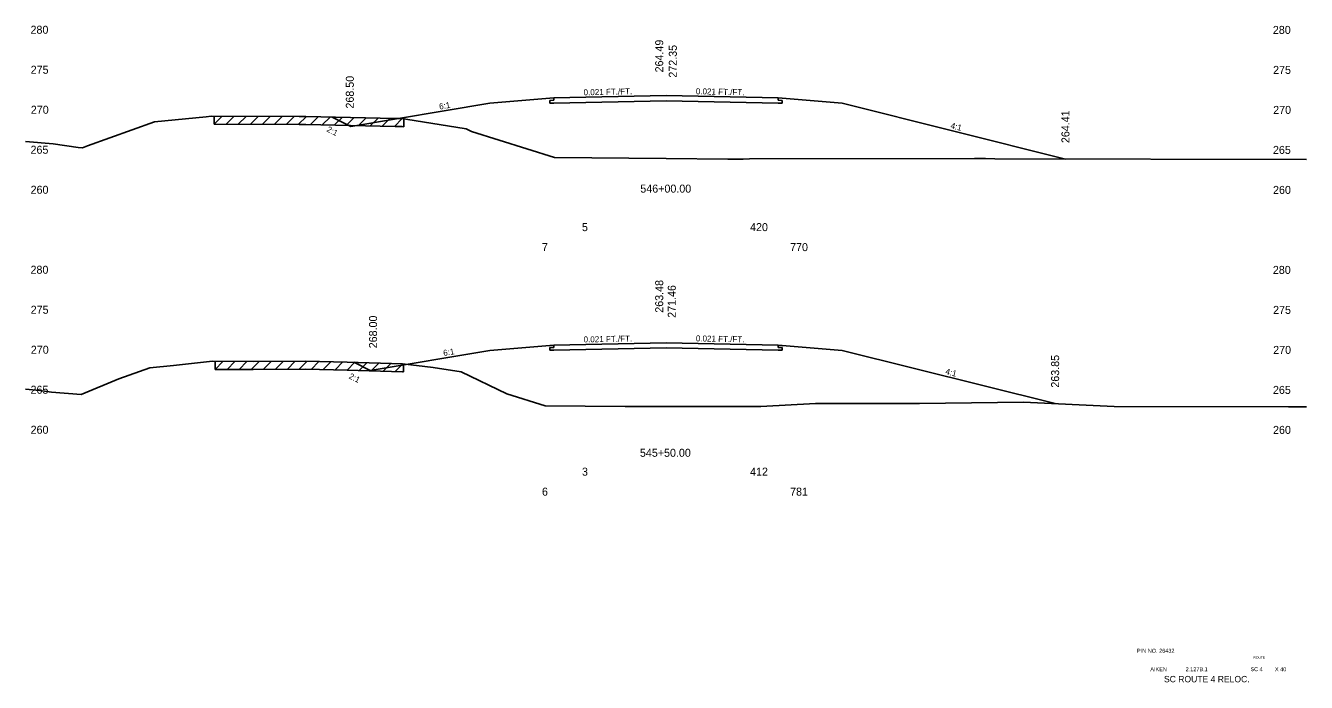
# Model space of a CAD drawing. Extents: x 2967 to 4323, y -3677 to -817.
# Drawn here: x 3555.3 to 3715.3, y -1970.8 to -1888.7 of the extents above; entities that cross this region are included whole.
import ezdxf

# ---------------------------------------------------------------- set-up
doc = ezdxf.new("R2010")
doc.units = 0
for name, color, linetype in [('Level 1', 7, 'Continuous'), ('Level 10', 7, 'Continuous'), ('Level 11', 7, 'Continuous'), ('Level 12', 7, 'Continuous'), ('Level 20', 7, 'Continuous'), ('Level 3', 7, 'Continuous'), ('Level 32', 7, 'Continuous'), ('Level 33', 7, 'Continuous'), ('Level 59', 7, 'Continuous'), ('Level 6', 7, 'Continuous'), ('Level 60', 7, 'Continuous'), ('Level 61', 7, 'Continuous'), ('Level 7', 7, 'Continuous')]:
    doc.layers.add(name, color=color, linetype=linetype)

msp = doc.modelspace()

# ---------------------------------------------------------------- linework, layer by layer
at = {"layer": 'Level 11'}
for p, q in [((3621.35, -1898.08), (3620.85, -1898.1)), ((3620.85, -1898.1), (3620.85, -1898.44)), ((3620.85, -1898.44), (3621.35, -1898.42)), ((3621.35, -1897.78), (3621.35, -1898.08)), ((3649.35, -1898.08), (3649.35, -1897.78)), ((3649.85, -1898.1), (3649.35, -1898.08)), ((3649.35, -1898.42), (3649.85, -1898.44)), ((3649.85, -1898.44), (3649.85, -1898.1)), ((3621.35, -1928.98), (3620.85, -1928.99)), ((3620.85, -1928.99), (3620.85, -1929.33)), ((3620.85, -1929.33), (3621.35, -1929.32)), ((3621.35, -1928.68), (3621.35, -1928.98)), ((3649.35, -1928.98), (3649.35, -1928.68)), ((3649.85, -1928.99), (3649.35, -1928.98)), ((3649.35, -1929.32), (3649.85, -1929.33)), ((3649.85, -1929.33), (3649.85, -1928.99))]:
    msp.add_line(p, q, dxfattribs=at)
at = {"layer": 'Level 12'}
for p, q in [((3635.35, -1898.13), (3621.35, -1898.42)), ((3649.35, -1898.42), (3635.35, -1898.13)), ((3635.35, -1929.03), (3621.35, -1929.32)), ((3649.35, -1929.32), (3635.35, -1929.03))]:
    msp.add_line(p, q, dxfattribs=at)
at = {"layer": 'Level 59'}
for p, q in [((3621.35, -1897.78), (3635.35, -1897.49)), ((3635.35, -1897.49), (3649.35, -1897.78)), ((3621.35, -1928.68), (3635.35, -1928.39)), ((3635.35, -1928.39), (3649.35, -1928.68))]:
    msp.add_line(p, q, dxfattribs=at)
at = {"layer": 'Level 6'}
for p, q in [((3613.35, -1898.45), (3621.35, -1897.78)), ((3649.35, -1897.78), (3657.35, -1898.45)), ((3613.35, -1929.34), (3621.35, -1928.68)), ((3649.35, -1928.68), (3657.35, -1929.34))]:
    msp.add_line(p, q, dxfattribs=at)
at = {"layer": 'Level 60'}
for p, q in [((3563.08, -1903.76), (3571.46, -1900.77)), ((3571.46, -1900.77), (3577.89, -1900.13)), ((3577.89, -1900.13), (3578.52, -1900.07)), ((3578.52, -1900.07), (3589.52, -1900.12)), ((3589.52, -1900.12), (3590.35, -1900.12)), ((3590.35, -1900.12), (3601.53, -1900.34)), ((3601.53, -1900.34), (3602.37, -1900.37)), ((3602.37, -1900.37), (3602.84, -1900.43)), ((3602.84, -1900.43), (3610.37, -1901.64)), ((3610.37, -1901.64), (3611.06, -1901.97)), ((3611.06, -1901.97), (3621.42, -1905.22)), ((3555.35, -1903.22), (3558.79, -1903.54)), ((3558.79, -1903.54), (3561.93, -1903.98)), ((3561.93, -1903.98), (3562.44, -1904.03)), ((3562.44, -1904.03), (3563.08, -1903.76)), ((3621.42, -1905.22), (3635.35, -1905.35)), ((3635.35, -1905.35), (3643.06, -1905.42)), ((3643.06, -1905.42), (3644.99, -1905.42)), ((3644.99, -1905.42), (3645.76, -1905.38)), ((3645.76, -1905.38), (3673.89, -1905.37)), ((3673.89, -1905.37), (3675.25, -1905.35)), ((3675.25, -1905.35), (3676.43, -1905.41)), ((3676.43, -1905.41), (3715.35, -1905.48)), ((3573.84, -1931.23), (3578.71, -1930.7)), ((3578.71, -1930.7), (3583.78, -1930.73)), ((3583.78, -1930.73), (3590.35, -1930.7)), ((3590.35, -1930.7), (3595.51, -1930.8)), ((3595.51, -1930.8), (3602.42, -1931.02)), ((3602.42, -1931.02), (3606.28, -1931.47)), ((3567.01, -1932.9), (3570.87, -1931.52)), ((3570.87, -1931.52), (3573.84, -1931.23)), ((3606.28, -1931.47), (3609.76, -1932.03)), ((3609.76, -1932.03), (3615.46, -1934.76)), ((3555.35, -1934.2), (3557.12, -1934.37)), ((3557.12, -1934.37), (3558.58, -1934.58)), ((3562.27, -1934.87), (3567.01, -1932.9)), ((3558.58, -1934.58), (3562.27, -1934.87)), ((3615.46, -1934.76), (3620.24, -1936.26)), ((3647.21, -1936.37), (3654.03, -1935.97)), ((3654.03, -1935.97), (3667.01, -1935.97)), ((3667.01, -1935.97), (3680.02, -1935.8)), ((3680.02, -1935.8), (3691.33, -1936.37)), ((3620.24, -1936.26), (3630.25, -1936.36)), ((3630.25, -1936.36), (3635.35, -1936.36)), ((3635.35, -1936.36), (3647.21, -1936.37)), ((3691.33, -1936.37), (3713.13, -1936.4)), ((3713.13, -1936.4), (3715.35, -1936.4))]:
    msp.add_line(p, q, dxfattribs=at)
at = {"layer": 'Level 61'}
for p, q in [((3579.91, -1900.07), (3578.91, -1901.07)), ((3578.91, -1900.07), (3578.91, -1901.07)), ((3581.41, -1900.08), (3580.41, -1901.08)), ((3582.91, -1900.09), (3581.91, -1901.08)), ((3584.41, -1900.1), (3583.41, -1901.09)), ((3585.91, -1900.1), (3584.91, -1901.1)), ((3587.41, -1900.11), (3586.41, -1901.1)), ((3588.91, -1900.12), (3587.91, -1901.11)), ((3590.42, -1900.12), (3589.41, -1901.12)), ((3591.89, -1900.15), (3590.91, -1901.13)), ((3593.39, -1900.18), (3592.41, -1901.16)), ((3594.89, -1900.21), (3593.91, -1901.19)), ((3596.39, -1900.24), (3595.41, -1901.22)), ((3597.89, -1900.27), (3596.91, -1901.25)), ((3599.39, -1900.3), (3598.41, -1901.28)), ((3600.89, -1900.33), (3599.91, -1901.31)), ((3602.38, -1900.37), (3601.41, -1901.34)), ((3602.58, -1901.39), (3602.58, -1900.39)), ((3578.91, -1901.07), (3589.52, -1901.12)), ((3589.52, -1901.12), (3590.35, -1901.12)), ((3590.35, -1901.12), (3601.53, -1901.34)), ((3601.53, -1901.34), (3602.37, -1901.37)), ((3602.37, -1901.37), (3602.58, -1901.39)), ((3580, -1930.71), (3579.01, -1931.71)), ((3579.01, -1930.71), (3579.01, -1931.71)), ((3581.5, -1930.72), (3580.51, -1931.71)), ((3583, -1930.73), (3582.01, -1931.72)), ((3584.51, -1930.73), (3583.51, -1931.73)), ((3586.01, -1930.72), (3585.01, -1931.72)), ((3587.51, -1930.71), (3586.51, -1931.72)), ((3589.01, -1930.7), (3588.01, -1931.71)), ((3590.51, -1930.7), (3589.51, -1931.7)), ((3591.99, -1930.73), (3591.01, -1931.71)), ((3593.49, -1930.76), (3592.51, -1931.74)), ((3594.99, -1930.79), (3594.01, -1931.77)), ((3596.48, -1930.83), (3595.51, -1931.8)), ((3597.98, -1930.88), (3597.01, -1931.85)), ((3599.48, -1930.92), (3598.51, -1931.89)), ((3600.98, -1930.97), (3600.01, -1931.94)), ((3602.47, -1931.02), (3601.51, -1931.99)), ((3602.55, -1932.03), (3602.55, -1931.03)), ((3579.01, -1931.71), (3583.78, -1931.73)), ((3583.78, -1931.73), (3590.35, -1931.7)), ((3590.35, -1931.7), (3595.51, -1931.8)), ((3595.51, -1931.8), (3602.42, -1932.02)), ((3602.42, -1932.02), (3602.55, -1932.03))]:
    msp.add_line(p, q, dxfattribs=at)
at = {"layer": 'Level 7'}
for p, q in [((3595.98, -1901.35), (3613.35, -1898.45)), ((3657.35, -1898.45), (3685.25, -1905.43)), ((3595.98, -1901.35), (3593.65, -1900.18)), ((3598.39, -1931.84), (3613.35, -1929.34)), ((3657.35, -1929.34), (3683.96, -1936)), ((3598.39, -1931.84), (3596.37, -1930.83))]:
    msp.add_line(p, q, dxfattribs=at)

# ---------------------------------------------------------------- texts
at = {"layer": 'Level 1'}
for s, p in [('5', (3624.85, -1914.43)), ('420', (3645.85, -1914.43)), ('7', (3619.85, -1916.93)), ('770', (3650.85, -1916.93)), ('3', (3624.85, -1945)), ('412', (3645.85, -1945)), ('6', (3619.85, -1947.5)), ('781', (3650.85, -1947.5))]:
    msp.add_text(s, height=1, dxfattribs=at).set_placement(p)
at = {"layer": 'Level 10'}
for s, p in [('264.49', (3635, -1894.59)), ('263.48', (3635, -1924.63))]:
    msp.add_text(s, height=1, rotation=90, dxfattribs=at).set_placement(p)
for s, p in [('546+00.00', (3632.14, -1909.62)), ('545+50.00', (3632.09, -1942.64))]:
    msp.add_text(s, height=1, dxfattribs=at).set_placement(p)
at = {"layer": 'Level 20'}
for s, height, p in [('PIN NO. 26432', 0.5, (3694.19, -1967.14)), ('ROUTE', 0.3, (3708.73, -1967.88)), ('AIKEN', 0.5, (3695.85, -1969.44)), (' 2.127B.1', 0.5, (3700.07, -1969.44)), ('SC 4', 0.5, (3708.36, -1969.44)), ('X 40', 0.5, (3711.42, -1969.45)), ('SC ROUTE 4 RELOC.', 0.8, (3697.56, -1970.83))]:
    msp.add_text(s, height=height, dxfattribs=at).set_placement(p)
at = {"layer": 'Level 3'}
for s, p in [(' 280', (3555.59, -1889.76)), (' 280', (3710.79, -1889.78)), (' 275', (3555.61, -1894.76)), (' 275', (3710.82, -1894.78)), (' 270', (3555.63, -1899.76)), (' 270', (3710.83, -1899.78)), (' 265', (3555.59, -1904.76)), (' 265', (3710.8, -1904.78)), (' 260', (3555.6, -1909.76)), (' 260', (3710.81, -1909.78)), (' 280', (3555.59, -1919.76)), (' 280', (3710.79, -1919.78)), (' 275', (3555.61, -1924.76)), (' 275', (3710.82, -1924.78)), (' 270', (3555.63, -1929.76)), (' 270', (3710.83, -1929.78)), (' 265', (3555.59, -1934.76)), (' 265', (3710.8, -1934.78)), (' 260', (3555.6, -1939.76)), (' 260', (3710.81, -1939.78))]:
    msp.add_text(s, height=1, dxfattribs=at).set_placement(p)
at = {"layer": 'Level 32'}
for s, rotation, p in [('0.021 FT./FT.', 1.1916, (3625.06, -1897.46)), ('0.021 FT./FT.', 358.8084, (3639.07, -1897.32)), ('6:1', 9.4623, (3607.07, -1899.24)), ('2:1', 333.435, (3592.88, -1901.95)), ('4:1', 345.9638, (3670.84, -1901.57)), ('0.021 FT./FT.', 1.1916, (3625.06, -1928.35)), ('0.021 FT./FT.', 358.8084, (3639.07, -1928.21)), ('6:1', 9.4623, (3607.58, -1930.05)), ('2:1', 333.435, (3595.65, -1932.81)), ('4:1', 345.9638, (3670.2, -1932.3))]:
    msp.add_text(s, height=0.75, rotation=rotation, dxfattribs=at).set_placement(p)
at = {"layer": 'Level 33'}
for s, p in [('268.50', (3596.35, -1899.11)), ('264.41', (3685.75, -1903.43)), ('268.00', (3599.25, -1929.08)), ('263.85', (3684.46, -1934))]:
    msp.add_text(s, height=1, rotation=90, dxfattribs=at).set_placement(p)
at = {"layer": 'Level 59'}
for s, p in [(' 272.35', (3636.7, -1895.62)), (' 271.46', (3636.57, -1925.64))]:
    msp.add_text(s, height=1, rotation=90, dxfattribs=at).set_placement(p)

doc.saveas('drawing.dxf')
